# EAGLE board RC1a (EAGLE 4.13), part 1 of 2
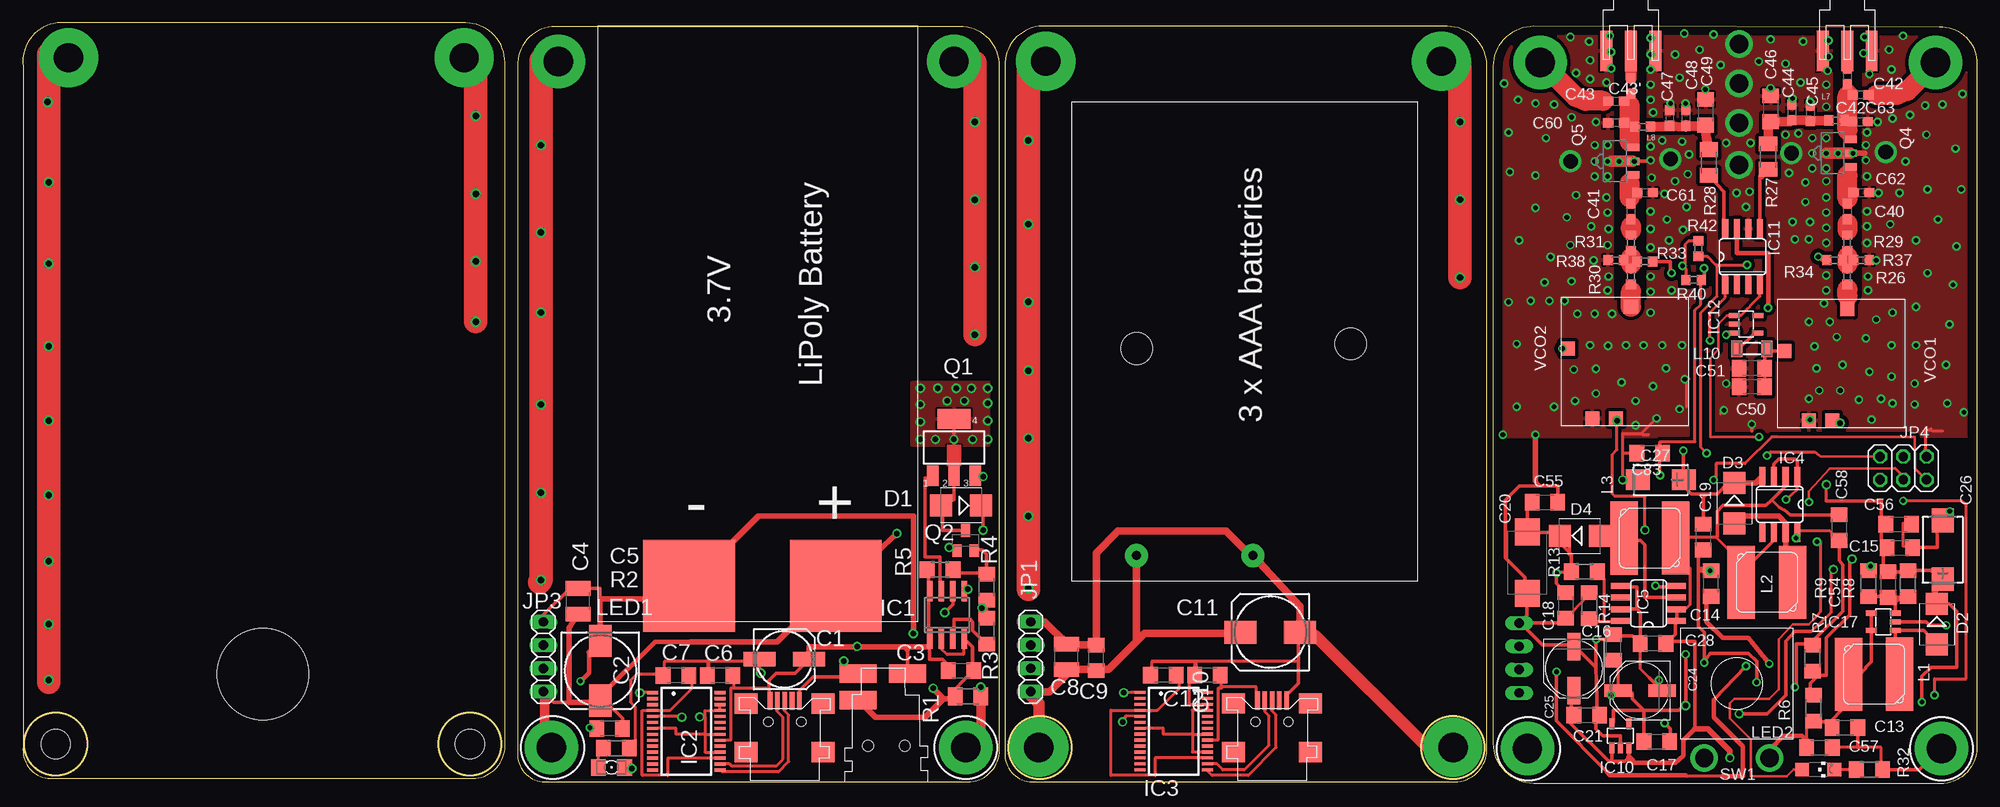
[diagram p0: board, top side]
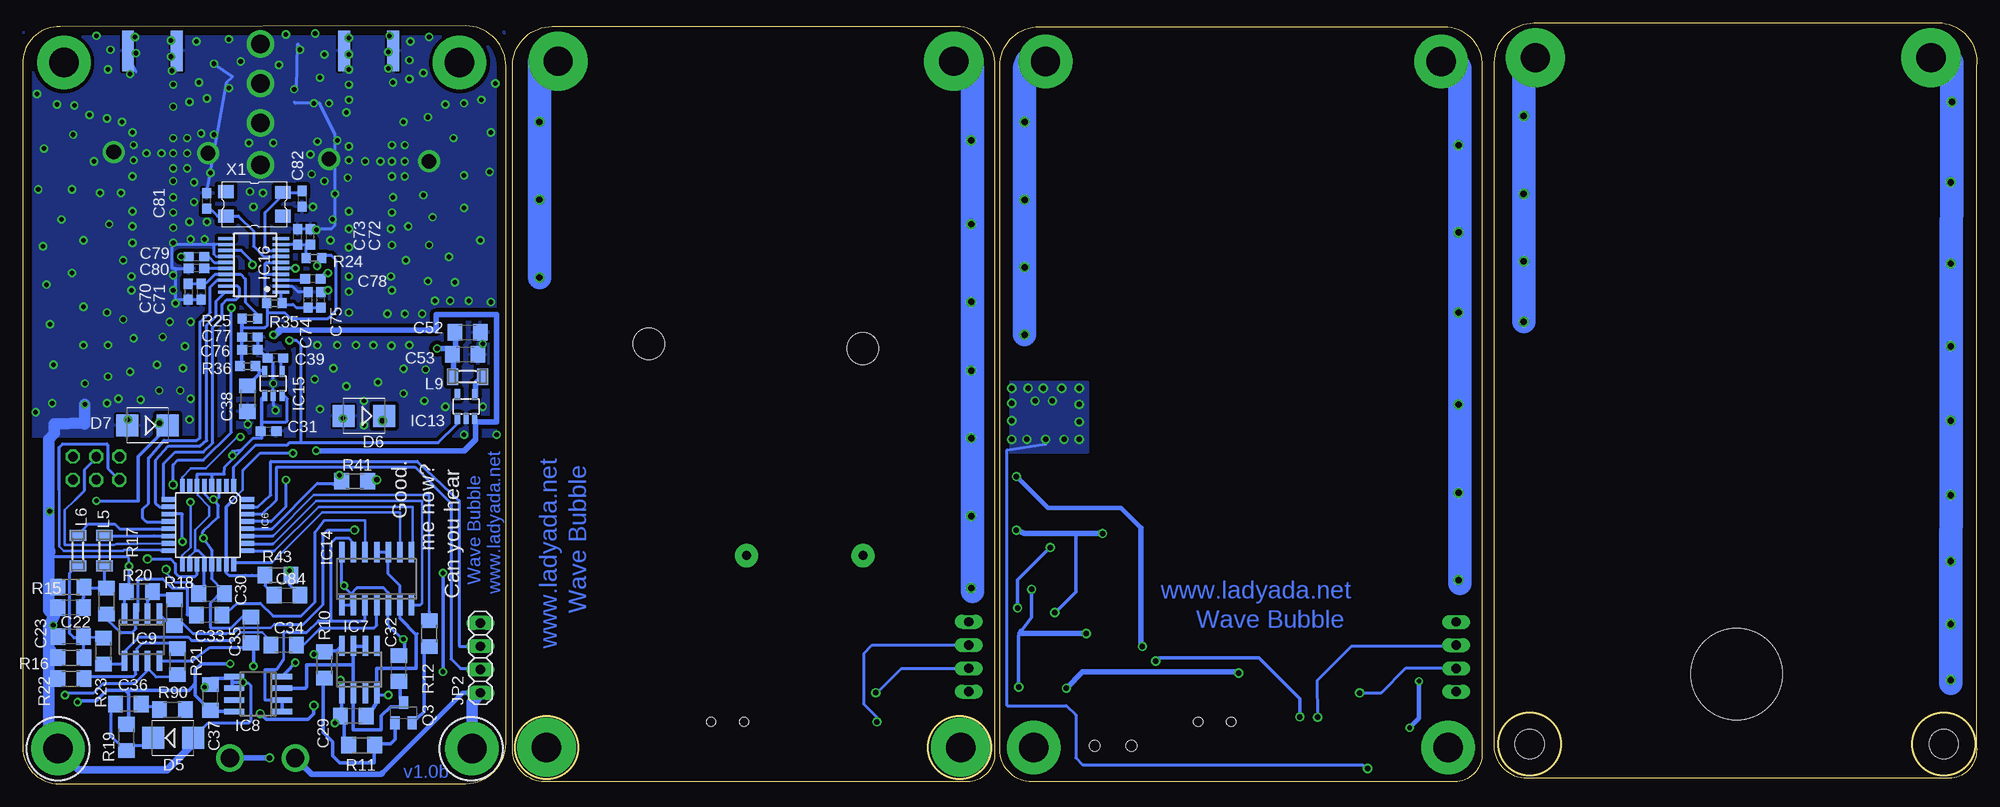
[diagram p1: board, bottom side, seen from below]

Size 213.27 x 83.09 mm. Coordinates in mm from the lower left corner, seen from the top.
Outline: 54.02,3.63 arc90 56.69,0.2 103.1,0.2 arc90 106.62,3.72 106.62,78.36 arc90 102.29,82.69 57.72,82.69 arc90 54.02,77.98 54.02,3.63
Outline: 107.22,3.65 arc90 109.89,0.21 156.3,0.21 arc90 159.82,3.73 159.82,78.38 arc90 155.49,82.71 110.92,82.71 arc90 107.22,77.99 107.22,3.65
Outline: 213.27,3.57 arc-90 208.96,0.02 164.93,0.02 arc-90 160.54,4.4 160.54,78.36 arc-90 164.95,82.75 209.19,82.65 arc-90 213.27,78.96 213.27,3.57
Outline: 0.03,4.03 arc90 2.7,0.59 49.12,0.59 arc90 52.63,4.11 52.63,78.76 arc90 48.3,83.09 3.73,83.09 arc90 0.03,78.37 0.03,4.03
Outline: circle at 156.11,3.97 radius 3.43
Outline: circle at 111.03,3.97 radius 3.43
Outline: circle at 48.8,4.35 radius 3.43
Outline: circle at 3.58,4.35 radius 3.43
Copper layers (1*16): Top 0.035mm / dielectric 1.5mm / Bottom 0.035mm
Design rules "default": minimum track width 10mil, minimum drill 24mil, track to track 8mil, track to pad 8mil, pad to pad 8mil, via to via 8mil, smd to smd 8mil, copper to edge 40mil, drill to drill 8mil, minimum pad ring 10mil, minimum via ring 8mil, stop-mask expansion 4mil, vias tented up to drill 0mil, thermal gap 10mil
Holes 3.2 mm at 48.8,4.35 3.58,4.35
Holes 10 mm at 26.19,11.97

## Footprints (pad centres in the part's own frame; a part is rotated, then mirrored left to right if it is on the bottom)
LIPOLY-65X34MM = smd 10 x 10: + -8,28.11; - 8,28.11
3AAA-PC = drill 1 pad 2.54 round: + 23.368,-11.938; - 23.368,0.762 | hole 3.454: 0.762,-11.938; 0.254,11.43
153CLV-0605 = smd 3.5 x 1.6: + 2.7,0; - -2.7,0
153CLV-0810 = smd 3.5 x 2.5: + 3.25,0; - -3.25,0
C1206 = smd 1.6 x 1.8: 1 -1.4,0; 2 1.4,0
C3225 = smd 1.6 x 2.7: 1 -1.4,0; 2 1.4,0
D/7343-31W = smd 2.95 x 2.7: + 3.375,0; - -3.375,0
PANASONIC_D = smd 3 x 1.4: + 2.4,0; - -2.4,0
CT7343 = smd 2.6 x 2.4: + 3.2,0; - -3.2,0
CT6032 = smd 2.6 x 2.2: + 2.5,0; - -2.5,0
C0603 = smd 1.1 x 1: 1 -0.85,0; 2 0.85,0
SMB = smd 2.4 x 2.4: A 2.2,0; C -2.2,0
SO08 = smd 0.6 x 2.2: 1 -1.905,-2.6; 2 -0.635,-2.6; 3 0.635,-2.6; 4 1.905,-2.6; 5 1.905,2.6; 6 0.635,2.6; 7 -0.635,2.6; 8 -1.905,2.6
TSSOP28 = smd 0.35 x 1.2: 1 -4.225,-3.7; 2 -3.575,-3.7; 3 -2.925,-3.7; 4 -2.275,-3.7; 5 -1.625,-3.7; 6 -0.975,-3.7; 7 -0.325,-3.7; 8 0.325,-3.7; 9 0.975,-3.7; 10 1.625,-3.7; 11 2.275,-3.7; 12 2.925,-3.7; 13 3.575,-3.7; 14 4.225,-3.7; 15 4.225,3.7; 16 3.575,3.7; 17 2.925,3.7; 18 2.275,3.7; 19 1.625,3.7; 20 0.975,3.7; 21 0.325,3.7; 22 -0.325,3.7; 23 -0.975,3.7; 24 -1.625,3.7; 25 -2.275,3.7; 26 -2.925,3.7; 27 -3.575,3.7; 28 -4.225,3.7
SO08' = smd 0.66 x 2.032: 1 -1.905,-3.073; 2 -0.635,-3.073; 3 0.635,-3.073; 4 1.905,-3.073; 5 1.905,3.073; 6 0.635,3.073; 7 -0.635,3.073; 8 -1.905,3.073
TQFP32-08 = smd 1.524 x 0.508: 1 -4.293,2.8; 2 -4.293,2; 3 -4.293,1.2; 4 -4.293,0.4; 5 -4.293,-0.4; 6 -4.293,-1.2; 7 -4.293,-2; 8 -4.293,-2.8; 17 4.293,-2.8; 18 4.293,-2; 19 4.293,-1.2; 20 4.293,-0.4; 21 4.293,0.4; 22 4.293,1.2; 23 4.293,2; 24 4.293,2.8 | smd 0.508 x 1.524: 9 -2.8,-4.293; 10 -2,-4.293; 11 -1.2,-4.293; 12 -0.4,-4.293; 13 0.4,-4.293; 14 1.2,-4.293; 15 2,-4.293; 16 2.8,-4.293; 25 2.8,4.293; 26 2,4.293; 27 1.2,4.293; 28 0.4,4.293; 29 -0.4,4.293; 30 -1.2,4.293; 31 -2,4.293; 32 -2.8,4.293
SOT23-5L = smd 0.55 x 1.2: 1 -0.95,-1.3; 2 0,-1.3; 3 0.95,-1.3; 4 0.95,1.3; 5 -0.95,1.3
SO14 = smd 0.6 x 2.2: 1 -3.81,-2.9; 2 -2.54,-2.9; 3 -1.27,-2.9; 4 0,-2.9; 5 1.27,-2.9; 6 2.54,-2.9; 7 3.81,-2.9; 8 3.81,2.9; 9 2.54,2.9; 10 1.27,2.9; 11 0,2.9; 12 -1.27,2.9; 13 -2.54,2.9; 14 -3.81,2.9
TSSOP-20 = smd 0.35 x 1.8: 1 -2.835,-3.023; 2 -2.195,-2.999; 3 -1.545,-2.999; 4 -0.895,-2.999; 5 -0.245,-2.999; 6 0.405,-2.999; 7 1.055,-2.999; 8 1.705,-2.999; 9 2.355,-2.999; 10 3.005,-2.999; 11 3.005,2.951; 12 2.355,2.951; 13 1.705,2.951; 14 1.055,2.951; 15 0.405,2.951; 16 -0.245,2.951; 17 -0.895,2.951; 18 -1.545,2.951; 19 -2.195,2.951; 20 -2.845,2.951
CLEANAIR_5MMJACK = smd 2 x 4: RING -9,-2.596; RING_SW -11.9,-2.6; TIP -11.9,2.8 | hole 1.2: -4,2.5; -4,-1.5
1X04 = drill 1.016 long: 1 -3.81,0; 2 -1.27,0; 3 1.27,0; 4 3.81,0
2X03 = drill 1.016 octagon: 1 -2.54,-1.27; 2 -2.54,1.27; 3 0,-1.27; 4 0,1.27; 5 2.54,-1.27; 6 2.54,1.27
CDRH6D28 = smd 3 x 8: L1 -2.8,-0.008; L2 2.8,0.008
SM-1206 = smd 1.2 x 1.8: 1 -1.65,0; 2 1.65,0
0603 = smd 1 x 1.1: 1 -0.875,0.025; 2 0.825,0.025
1206 = smd 1.6 x 1.803: A -1.422,0; C 1.422,0
CHIPLED_1206 = smd 1.5 x 1.5: A 0,-1.75; C 0,1.75
SOT223 = smd 1.219 x 2.235: 1 -2.311,-3.099; 2 0,-3.099; 3 2.311,-3.099 | smd 3.6 x 2.2: 4 0,3.099
SOT23-BEC = smd 1 x 1.4: B -0.95,-1.1; C 0,1.1; E 0.95,-1.1
SOT89 = smd 0.8 x 1.4: 1 -1.499,-1.981; 2 0,-1.981; 3 1.499,-1.981
M1206 = smd 1.6 x 2: 1 -1.4,0; 2 1.4,0
R1206 = smd 1.6 x 1.803: 1 -1.422,0; 2 1.422,0
R0603 = smd 1 x 1.1: 1 -0.85,0; 2 0.85,0
JUDCOSPST = drill 2 round: P 3.556,-8.128; T -3.556,-8.128
UX60A-MB-5SY = smd 0.5 x 2: 1 -1.6,2.3; 2 -0.8,2.3; 3 0,2.3; 4 0.8,2.3; 5 1.6,2.3 | smd 2.5 x 2.2: C1 -4.2,2; C2 -4.2,-3.3; C3 4.2,-3.3; C4 4.2,2 | hole 1.016: -1.8,0; 1.8,0
SMA-ANTENNA = smd 1.27 x 4.445: COND 0,-2.794; GND3 -2.667,-2.794; GND4 2.667,-2.794 | smd 1.27 x 4.445 bottom: GND -2.667,-2.794; GND2 2.667,-2.794
MINICIRCUITS_KG = smd 1.524 x 1.524: P$1 3.429,0.762; P$2 5.969,0.762; P$10 7.62,12.954; P$14 0.762,8.382
ABMM = smd 1.7 x 1.4: NC 3.1,-1.3; NC2 -3.1,1.4; X1 -3.1,-1.3; X2 3.1,1.3

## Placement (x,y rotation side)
BAT1  [LIPOLY-65X34MM]  80.72,49.72 180 top
BAT2  [3AAA-PC]  133.51,48.29 270 top
C1  47uF/16V  [153CLV-0605]  83.1,13.6 0 top
C2  220uF  [153CLV-0810]  63.03,12.33 270 top
C3  .1uF  [C1206]  102.4,12.33 0 top
C4  1uF  [C3225]  60.6,19.93 90 top
C5  .1uF  [C1206]  64.04,6.04 180 top
C6  .1uF  [C1206]  76.11,11.83 180 top
C7  .1uF  [C1206]  71.29,11.83 180 top
C8  1uF  [C3225]  113.93,13.85 90 top
C9  .1uF  [C1206]  117.17,13.75 90 top
C10  .1uF  [C1206]  124.49,11.84 180 top
C11  220uF  [153CLV-0810]  136.17,16.54 180 top
C12  .1uF  [C1206]  129.31,11.84 180 top
C13  .1uF  [C1206]  198.9,6.14 0 top
C14  .1uF  [C1206]  184.29,21.86 90 top
C15  .1uF  [C1206]  204.89,25.79 0 top
C16  1uF  [C1206]  173.63,14.9 90 top
C17  .1uF  [C1206]  178.35,4.61 0 top
C18  .1uF  [C1206]  168.42,19.47 270 top
C19  .1uF  [C1206]  183.4,26.94 270 top
C20  22uF/35V  [D/7343-31W]  164.22,24.15 90 top
C21  .1uF  [C1206]  170.7,7.51 0 top
C22  4.7uF  [C1206]  208.07,19.22 180 bottom
C23  4.7uF  [C1206]  208.04,16.05 180 bottom
C24  100uF/4V  [PANASONIC_D]  176.54,10.18 180 top
C25  100uF/6.3  [PANASONIC_D]  169.3,12.59 270 top
C26  100uF/10V  [CT7343]  209.56,25.55 270 top
C27  68uF/16V  [CT6032]  178.8,33.19 0 top
C28  .1uF  [C1206]  177.95,15.28 180 top
C29  .1uF  [C1206]  177.2,7.38 180 bottom
C30  .1uF  [C1206]  192.68,20.74 0 bottom
C31  .1uF  [C0603]  186.45,38.5 0 bottom
C32  .1uF  [C1206]  172.23,12.59 90 bottom
C33  4.7uF  [C1206]  192.93,18.43 180 bottom
C34  4.7uF  [C1206]  184.8,15.13 180 bottom
C35  .1uF  [C1206]  188.35,16.78 90 bottom
C36  .47uF  [C1206]  201.75,8.69 180 bottom
C37  .1uF  [C1206]  192.8,9.42 90 bottom
C38  1.0uF  [C1206]  188.74,42.06 270 bottom
C39  .01uF  [C0603]  185.69,46.5 180 bottom
C40  68pF  [C0603]  199.15,62.5 270 top
C41  100pF  [C0603]  175.53,62.5 270 top
C42  68pF  [C0603]  199.15,77.23 270 top
C42'  68pF  [C0603]  200.62,75.22 180 top
C43  100pF  [C0603]  175.53,76.22 270 top
C43'  100pF  [C0603]  173.94,74.52 0 top
C44  1000pF  [C0603]  193.08,73.32 270 top
C45  22pF  [C0603]  195.12,73.19 270 top
C46  .1uF  [C1206]  190.8,73.7 270 top
C47  1000pF  [C0603]  179.75,72.68 270 top
C48  68pF  [C0603]  181.53,72.68 270 top
C49  .1uF  [C1206]  183.69,73.32 270 top
C50  1uF  [C1206]  188.74,43.33 180 top
C51  0.1uF  [C1206]  188.74,45.36 180 top
C52  1uF  [C1206]  164.73,49.29 0 bottom
C53  0.1uF  [C1206]  164.99,46.88 0 bottom
C54  160pF  [C1206]  203.61,21.75 270 top
C55  1.0uF  [C1206]  166.14,30.76 0 top
C56  1.0uF  [C1206]  204.75,28.35 0 top
C57  1.0uF  [C1206]  196.12,3.97 0 top
C58  1.0uF  [C1206]  198.28,27.97 270 top
C60  3.9pF  [C0603]  173.89,72.16 180 top
C61  5.6pF  [C0603]  177.07,64.54 0 top
C62  0pF  [C0603]  200.69,64.54 0 top
C63  1.0pF  [C0603]  200.56,72.29 0 top
C70  .01uF  [C0603]  195.21,53.74 270 bottom
C71  100pf  [C0603]  193.82,53.74 270 bottom
C72  100pf  [C0603]  181.88,59.71 90 bottom
C73  .01uF  [C0603]  183.27,59.71 90 bottom
C74  100pf  [C0603]  182.13,52.85 90 bottom
C75  .01uF  [C0603]  180.73,52.85 90 bottom
C76  .1uF  [C0603]  188.48,47.39 0 bottom
C77  4.7uF  [C0603]  188.48,48.79 0 bottom
C78  100pf  [C0603]  181.62,55.14 180 bottom
C79  100pf  [C0603]  194.32,57.55 0 bottom
C80  100pf  [C0603]  194.32,56.28 180 bottom
C81  20pF  [C0603]  193.21,63.64 90 bottom
C82  20pF  [C0603]  182.79,63.89 270 bottom
C83  0.1uF  [C1206]  177.57,36.1 180 top
C84  0.1uF  [C1206]  184.43,20.6 0 bottom
D1  1N5818  [SMB]  102.4,30.37 180 top
D2  1N5817  [SMB]  208.93,17.42 270 top
D3  1N5817  [SMB]  186.83,30.63 270 top
D4  1N5817  [SMB]  169.97,27.06 0 top
D5  1N5235  [SMB]  196.87,5 0 bottom
D6  1N5817  [SMB]  176.04,40.15 180 bottom
D7  1N5817  [SMB]  199.68,39.13 180 bottom
IC1  LM3622  [SO08]  100.88,18.43 0 top
IC2  FT232R  [TSSOP28]  72.43,5.73 270 top
IC3  FT232R  [TSSOP28]  125.63,5.74 270 top
IC4  LT1301  [SO08']  191.78,30.5 180 top
IC5  LT1173CS  [SO08']  177.46,19.7 90 top
IC6  ATMEGA48-20A  [TQFP32-08]  193.07,28.24 270 bottom
IC7  NE555D  [SO08]  176.54,12.46 0 bottom
IC8  LM358D  [SO08]  187.59,9.8 90 bottom
IC9  LM358D  [SO08]  200.29,16.02 180 bottom
IC10  TPS79333  [SOT23-5L]  174.38,5.23 0 top
IC11  MIC2506BM  [SO08']  187.72,57.55 0 top
IC12  MIC2514  [SOT23-5L]  188.1,50.18 270 top
IC13  MIC2514  [SOT23-5L]  164.89,41.19 0 bottom
IC14  AD8402  [SO14]  174.65,22.38 0 bottom
IC15  LP2985  [SOT23-5L]  185.94,43.71 0 bottom
IC16  LMX243X  [TSSOP-20]  188.1,56.53 90 bottom
IC17  LM2733  [SOT23-5L]  203.1,17.68 90 top
J1  CLEANAIR_POWERJACK163-2217  [CLEANAIR_5MMJACK]  93.77,0.14 270 top
JP1  [1X04]  110.01,13.87 90 top
JP2  [1X04]  163.34,13.73 90 bottom
JP3  [1X04]  56.81,13.86 90 top
JP4  [2X03]  205.28,34.46 0 top
L1  15uH  [CDRH6D28]  202.07,11.96 0 top
L2  33uH  [CDRH6D28]  190.39,21.99 0 top
L3  33uH  [CDRH6D28]  177.59,26.84 180 top
L5  1K  [SM-1206]  204.36,25.44 270 bottom
L6  1K  [SM-1206]  207.28,25.44 270 bottom
L7  22nH  [0603]  198.01,72.41 0 top
L8  33nH  [0603]  176.8,71.77 180 top
L9  0  [SM-1206]  164.73,44.47 0 bottom
L10  0  [SM-1206]  188.74,47.52 0 top
LED1  [1206]  64.25,1.78 180 top
LED2  [CHIPLED_1206]  195.97,1.54 270 top
Q1  [SOT223]  101.64,36.72 0 top
Q2  MMBT3906  [SOT23-BEC]  102.91,26.56 0 top
Q3  3906  [SOT23-BEC]  171.72,7.77 0 bottom
Q4  SXA-389B  [SOT89]  197.51,68.86 90 top
Q5  SXA-389B  [SOT89]  173.76,67.97 90 top
R1  0.25  [M1206]  103.17,9.54 0 top
R2  2K  [R1206]  64.78,3.88 180 top
R3  4.7K  [R1206]  105.2,16.65 90 top
R4  47K  [R1206]  105.2,21.48 90 top
R5  100  [R1206]  100.12,23.38 0 top
R6  510K  [R1206]  195.47,8.27 270 top
R7  220K  [R1206]  195.34,13.73 270 top
R8  37K  [R1206]  205.78,21.86 90 top
R9  12K  [R1206]  201.46,21.86 270 top
R10  10K  [R1206]  180.35,12.97 90 bottom
R11  20K  [R1206]  176.29,4.21 0 bottom
R12  100  [R1206]  168.92,16.4 90 bottom
R13  1M  [R1206]  170.45,23.16 180 top
R14  50K  [R1206]  170.98,19.44 270 top
R15  (adj)  [R1206]  208.04,21.48 180 bottom
R16  (adj)  [R1206]  208.04,13.76 180 bottom
R17  10K  [R1206]  204.13,19.95 270 bottom
R18  100K  [R1206]  196.74,18.69 270 bottom
R19  2K  [R1206]  201.98,5.06 270 bottom
R20  10K  [R1206]  200.55,21 0 bottom
R21  100K  [R1206]  196.38,13.35 270 bottom
R22  10K  [R1206]  208.04,11.47 0 bottom
R23  10K  [R1206]  204.48,14.5 270 bottom
R24  18  [R0603]  181.5,57.42 0 bottom
R25  18  [R0603]  188.48,50.82 0 bottom
R26  18  [R0603]  199.15,55.39 270 top
R27  0  [M1206]  190.51,68.47 270 top
R28  0  [M1206]  184.04,67.84 270 top
R29  18  [R0603]  199.15,59.07 270 top
R30  18  [R0603]  175.53,55.39 270 top
R31  18  [R0603]  175.53,59.07 270 top
R32  2K  [R1206]  201.56,1.54 0 top
R33  50  [R0603]  177.05,57.04 0 top
R34  50  [R0603]  197.75,57.17 180 top
R35  18  [R0603]  185.81,52.47 180 bottom
R36  18  [R0603]  188.74,45.61 180 bottom
R37  0  [R0603]  200.69,57.18 0 top
R38  68  [R0603]  173.89,57.18 180 top
R40  10k  [R0603]  182.39,55.01 0 top
R41  10k  [R1206]  177.05,33.04 0 bottom
R42  10k  [R0603]  182.89,58.44 270 top
R43  10k  [R1206]  185.44,22.78 180 bottom
R90  100K  [R1206]  196.93,8.08 180 bottom
SW1  SPST  [JUDCOSPST]  187.1,10.95 0 top
U$1  MINIUSB  [UX60A-MB-5SY]  136.36,6.77 0 top
U$6  MINIUSB  [UX60A-MB-5SY]  83.16,6.76 0 top
U$8  SMAANTENNA  [SMA-ANTENNA]  175.53,82.82 0 top
U$9  SMAANTENNA  [SMA-ANTENNA]  199.15,82.82 0 top
VCO1  ROS2500  [MINICIRCUITS_KG]  191.53,38.88 0 top
VCO2  ROS1200  [MINICIRCUITS_KG]  167.91,39.13 0 top
X1  10.000 MHz  [ABMM]  187.99,63.27 0 bottom

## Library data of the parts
BAT1 BAT2 IC4 IC5 IC10-IC17 L1-L3 L7 L8 Q4 Q5 U$1 U$6 U$8 U$9 VCO1 VCO2 = cleanair
C1-C42 C42' C43 C43' C44-C58 C60-C63 C70-C84 R1-R38 R40-R43 R90 = rcl
D1-D7 = diode
IC1 = liion
IC2 IC3 = ft232
IC6 = avr
IC7-IC9 = linear
J1 = cigpack-batt_lm3622
JP1-JP4 = pinhead
L5 L6 L9 L10 = inductor-neosid
LED1 LED2 = led
Q1 = zetex
Q2 Q3 = transistor-pnp
SW1 X1 = cigpack-main_rc1

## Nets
+6V: C14.1 C15.1 C26.+ C37.1 C54.1 C56.1 D2.C IC8.8 IC11.7 R8.2 R19.1
+12V: C19.1 C27.+ D3.C IC4.4 IC12.3 IC13.3
+24V: C18.1 C20.+ C35.1 C55.1 D4.C IC9.8 R13.2
CLK: IC6.24 IC14.9
CP_IF: C83.1 IC6.28 IC16.5 R40.2 R41.1
CP_RF: C84.1 IC6.23 IC16.13 R42.2 R43.2
D+: IC2.15 U$6.3
D+1: IC3.16 U$1.2
D-: IC2.16 U$6.2
D-1: IC3.15 U$1.3
FB: IC5.8 R13.1 R14.2
GND: C1.- C3.2 C6.2 C7.2 IC1.2 IC1.4 J1.RING R1.1 R2.1
GND1: BAT2.- C8.2 C9.2 C10.2 C11.- C12.2 IC3.7 IC3.18 IC3.21 IC3.25 IC3.26 JP1.4 U$1.5
GND2: C13.2 C14.2 C15.2 C16.2 C17.2 C18.2 C19.2 C20.- C21.2 C22.2 C23.2 C24.- C25.- C26.- C27.- C28.2 C29.2 C30.2 C31.2 C32.2 C35.2 C37.2 C38.2 C39.2 C44.1 C45.1 C46.1 C47.1 C48.1 C49.1 C50.2 C51.2 C52.2 C53.2 C55.2 C56.2 C57.2 C58.2 C60.2 C61.2 C62.2 C63.2 C70.2 C71.2 C72.2 C73.2 C74.2 C75.2 C76.2 C77.2 C80.2 C81.2 C82.2 C83.2 C84.2 D5.A D6.A D7.A IC4.1 IC4.3 IC4.8 IC5.4 IC5.5 IC5.7 IC6.3 IC6.5 IC6.21 IC7.1 IC8.4 IC8.5 IC8.6 IC9.4 IC10.2 IC11.6 IC12.2 IC13.2 IC14.1 IC14.2 IC14.5 IC14.14 IC15.2 IC16.2 IC16.12 IC16.14 IC17.2 JP2.4 JP4.6 Q4.2 Q5.2 R7.1 R9.1 R11.1 R14.1 R15.2 R16.2 R20.1 R22.1 R32.2 R37.2 R38.2 R41.2 R43.1 U$8.GND U$8.GND2 U$8.GND3 U$8.GND4 U$9.GND U$9.GND2 U$9.GND3 U$9.GND4 VCO1.P$1 VCO2.P$1
LBI: IC6.19 R6.1 R7.2
MISO: IC6.16 JP4.1
N$1: BAT1.- C2.- C4.2 C5.2 IC1.5 JP3.4 R1.2
N$2: IC2.7 IC2.18 IC2.21 IC2.25 IC2.26 J1.RING_SW U$6.5
N$3: LED1.C R2.2
N$4: IC1.3 R3.1
N$5: Q2.B R3.2 R4.1
N$6: Q2.E R4.2 R5.2
N$7: D1.A LED1.A Q1.4 Q2.C
N$8: BAT1.+ C2.+ C4.1 C5.1 D1.C IC1.6 JP3.1
N$9: IC1.7 Q1.1
N$10: IC2.1 JP3.2
N$11: BAT2.+ C8.1 C9.1 C11.+ JP1.1
N$12: C10.1 IC3.4 IC3.17
N$13: IC3.5 JP1.3
N$14: C12.1 IC3.20 U$1.1
N$15: IC3.1 JP1.2
N$16: D2.A IC17.1 L1.L2
N$17: C7.1 IC2.4 IC2.17
N$18: D3.A IC4.7 L2.L2
N$19: Q3.B R10.1 R11.2
N$20: C32.1 IC7.2 IC7.6 IC7.7 IC8.3 Q3.C
N$21: IC8.1 IC8.2 IC14.3 IC14.13
N$22: C33.1 IC14.12
N$23: D4.A IC5.3 L3.L2
N$24: C36.2 D5.C R19.2
N$25: C79.1 R34.2
N$26: IC6.26 IC14.7
N$27: C33.2 IC9.3 R17.2
N$28: IC9.2 R18.1 R20.2
N$29: IC9.6 R21.1 R22.2
N$30: C34.1 IC14.4
N$31: C36.1 R90.2
N$32: C47.2 C48.2 C49.2 L8.1 R28.1
N$33: C34.2 IC9.5 R23.2
N$34: IC6.14 L5.1
N$35: IC6.13 L6.1
N$35R: C43'.2 C43.2 C60.1 L8.2 Q5.3
N$36: R26.2 VCO1.P$10
N$37: IC11.8 R28.2
N$38: C44.2 C45.2 C46.2 L7.1 R27.1
N$39: C52.1 C53.1 L9.1 VCO2.P$14
N$40: IC13.4 L9.2
N$41: IC2.5 JP3.3
N$42: C40.2 R29.1
N$43: C42'.2 C42.2 C63.1 L7.2 Q4.3
N$44: IC12.4 L10.1
N$45: C50.1 C51.1 L10.2 VCO1.P$14
N$46: C82.1 IC16.8 X1.X2
N$47: R30.2 VCO2.P$10
N$48: C80.1 IC16.16
N$49: C41.2 R31.1
N$50: C78.1 R33.2
N$51: C78.2 IC16.3
N$52: C79.2 IC16.15
N$53: C39.1 IC15.4
N$54: C76.1 C77.1 IC16.4 IC16.6 R24.2 R25.1 R35.2 R36.2 R40.1 R42.1
N$55: Q3.E R12.1
N$56: IC6.27 R12.2
N$57: JP2.1 SW1.T
N$58: IC11.5 R27.2
N$59: C41.1 C61.1 Q5.1
N$60: LED2.C R32.1
N$61: C40.1 C62.1 Q4.1
N$62: IC6.1 IC11.1 IC13.1
N$63: IC6.17 JP4.3
N$64: IC6.15 JP4.4
N$65: IC6.11 LED2.A
N$664: IC6.8 IC11.4 IC12.1
N$666: C81.1 IC16.7 X1.X1
N$10077: C74.1 C75.1 IC16.1 R35.1
PLL_CLK: IC6.9 IC16.19
PLL_DATA: IC6.10 IC16.20
PLL_LE: IC6.12 IC16.18
RESET: IC6.29 JP4.5
RF_OUT: C43.1 U$8.COND
RF_OUT1: C42.1 U$9.COND
RX: IC6.30 JP2.2
SDI: IC6.25 IC14.8
SENSE: C54.2 IC17.3 R8.1 R9.2
STRIPLINE1: C42'.1
STRIPLINE2: C43'.1
TX: IC6.31 JP2.3
VCC: C1.+ C3.1 C6.1 IC1.1 IC1.8 IC2.20 J1.TIP Q1.3 R5.1 U$6.1
VCC1: C16.1 C17.1 C24.+ C29.1 C30.1 C31.1 IC6.4 IC6.6 IC6.18 IC6.20 IC7.4 IC7.8 IC10.5 IC14.6 IC14.10 IC14.11 IC15.1 IC15.3 JP4.2 R10.2
VCC2: C70.1 C71.1 IC16.17 R25.2
VCC3: C72.1 C73.1 IC16.9 R24.1
VCO1_DCADJ: C23.1 L6.2 R16.1 R23.1
VCO1_OUT: R26.1 R29.2 R34.1 R37.1
VCO1_TUNE: D7.C IC9.7 R21.2 VCO1.P$2
VCO2_DCADJ: C22.1 L5.2 R15.1 R17.1
VCO2_OUT: R30.1 R31.2 R33.1 R38.1
VCO2_TUNE: D6.C IC9.1 R18.2 VCO2.P$2
VIN: C13.1 C21.1 C25.+ C28.1 C57.1 C58.1 IC4.2 IC4.6 IC5.1 IC5.2 IC10.1 IC10.3 IC17.4 IC17.5 L1.L1 L2.L1 L3.L1 R6.2 SW1.P
VPP: C38.1 IC15.5 R36.1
